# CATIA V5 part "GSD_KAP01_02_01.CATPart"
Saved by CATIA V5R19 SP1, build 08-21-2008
Part number: GSD_ERSTER_START
Description: Beispielmodell Grundlagen, erster CATIA-Start  Maik Hertha IT Consultants
Bounding box of the stored display mesh (mm): x -19 to 20, y -24.424 to 63.985, z -21.041 to 27.25
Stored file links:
  \GSD_BUCH_UEBUNG\GSD_KAP01_02_01.CATPart
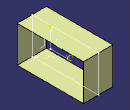
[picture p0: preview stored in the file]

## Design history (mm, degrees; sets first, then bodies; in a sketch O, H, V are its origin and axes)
AxisSystem1: origin (0, 0, 0), X (1, 0, 0), Y (0, 1, 0), Z (0, 0, 1)
Set1
  Sketch1 on YZ plane of AxisSystem1, origin (0, 0, 0), H (0, 1, 0), V (0, 0, 1)
    line L1 (-24.4242, 27.2503) -> (63.9846, 27.2503)
    line L2 (63.9846, 27.2503) -> (63.9846, -21.0414)
    line L3 (63.9846, -21.0414) -> (-24.4242, -21.0414)
    line L4 (-24.4242, -21.0414) -> (-24.4242, 27.2503)
    horizontal: L1 H, L3 H
    vertical: L2 V, L4 V
  Extrude1: Lim1 20, Lim2 19, Element1 Sketch1
Body1 (main body)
